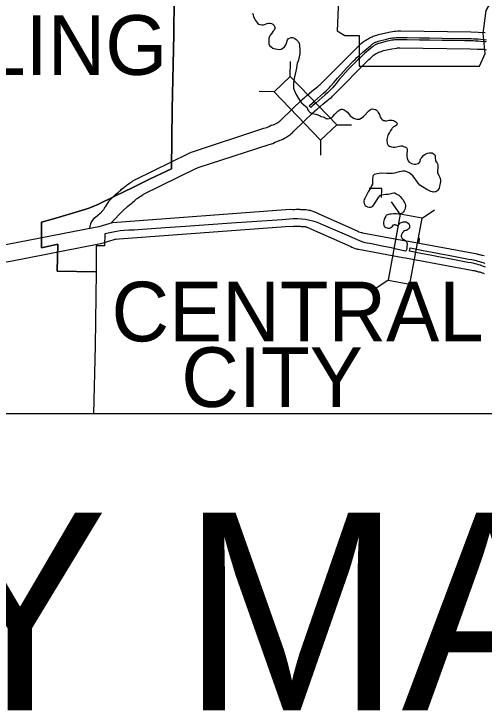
# Model space of a CAD drawing. Extents: x 535214 to 694517, y 381272 to 484355.
# Drawn here: x 552790 to 556953, y 445525 to 451713 of the extents above; entities that cross this region are included whole.
import ezdxf

# ---------------------------------------------------------------- set-up
doc = ezdxf.new("R2010")
doc.units = 0
for name, color, linetype in [('1', 7, 'Continuous'), ('2', 7, 'Continuous'), ('Level 10', 7, 'Continuous'), ('Level 20', 7, 'Continuous'), ('Level 21', 7, 'Continuous'), ('Level 6', 7, 'Continuous'), ('Level 7', 7, 'Continuous')]:
    doc.layers.add(name, color=color, linetype=linetype)

msp = doc.modelspace()

# ---------------------------------------------------------------- linework, layer by layer
at = {"layer": '1'}
msp.add_lwpolyline([(535213.7, 480223.3), (566227, 480223.3), (566227, 448175.2), (535213.7, 448175.2)], close=True, dxfattribs=at)
at = {"layer": 'Level 10'}
for points in [[(553627.3, 450054.3), (553650, 450077.3), (553695.3, 450119.9), (553714.8, 450136.9), (553727.9, 450148), (553734.9, 450153.3), (553742.6, 450161.9), (553763.7, 450177.8), (553769.6, 450182.9), (553777.5, 450189.5), (553785.4, 450195.8), (553791, 450199.8), (553803, 450209.4), (553811.6, 450214), (553813.4, 450215.2), (553822.8, 450222.5), (553832.4, 450228.2), (553839.5, 450232.9), (553843.2, 450235.5), (553849, 450240.4), (553864.5, 450249.5), (554334.5, 450479.1), (554346.9, 450485.2), (554357.7, 450489.5), (554369.6, 450494.4), (555003.6, 450701.2), (555027.7, 450708.7), (555041.3, 450714.9), (555048.4, 450717.2), (555052.8, 450719.3), (555068, 450728), (555081.9, 450731.4), (555085, 450732.6), (555094.1, 450736.5), (555100.8, 450738.7), (555105.7, 450741.1), (555112.8, 450744.6), (555119, 450748.3), (555122.5, 450750.4), (555125.4, 450752.6), (555135.2, 450759), (555140.5, 450762.3), (555142, 450763.4), (555146, 450766.5), (555153.1, 450772.6), (555154.3, 450773.4), (555158.7, 450778.4), (555339.9, 450953.1), (555344.1, 450957), (555348.6, 450962.5), (555358.6, 450971.4), (555365.2, 450977), (555370.8, 450981.2), (555379, 450987.5), (555383.9, 450990.8), (555428.4, 451029), (555479.8, 451071.9), (555489.3, 451078.9), (555494.9, 451083.1), (555498.8, 451086.1), (555502.9, 451089.5), (555505, 451092.1), (555512.9, 451100.5), (555830.9, 451419.9), (555840.8, 451428.5), (555846.4, 451434.1), (555851.7, 451438.9), (555856.2, 451443.8), (555866.5, 451453.9), (555878.9, 451463.2), (555886.5, 451468.9), (555895.2, 451475), (555902.4, 451479.9), (555913.5, 451489), (555926.5, 451494.8), (555935.9, 451499.6), (555945.2, 451504.7), (555957.5, 451510), (555963.5, 451512.4), (555972, 451516.1), (555982.1, 451520), (555992.7, 451523.7), (556002.1, 451526.7), (556009, 451529.3), (556018.8, 451533.1), (556109.1, 451553.9), (556156.4, 451560.2), (556167.1, 451562.1), (556187.3, 451564.5), (556200, 451565.7), (556213.2, 451564.4), (556215.8, 451564.2), (556835.8, 451554.5), (556900.3, 451551.4), (556961.9, 451550.3)], [(553653.4, 449866.8), (553754.8, 449970), (553796, 450008.7), (553812.8, 450023.3), (553821.9, 450031), (553837, 450042.5), (553844.4, 450050.8), (553857.5, 450060.7), (553866.6, 450068.4), (553872.9, 450073.7), (553876.1, 450076.3), (553881.5, 450080.1), (553885.6, 450083.4), (553890, 450085.7), (553902.3, 450094.4), (553907, 450098), (553912.4, 450101.2), (553924.4, 450109.3), (553934.8, 450116.5), (553935.9, 450117.5), (554400.4, 450344.3), (554408, 450348.1), (554414.2, 450350.6), (554421.4, 450353.5), (555049.2, 450558.3), (555081.2, 450568.3), (555095.6, 450574.8), (555103.5, 450577.4), (555122.2, 450586.1), (555122.7, 450586.4), (555141.1, 450593.4), (555148, 450596.4), (555158.4, 450599.9), (555171.6, 450606.4), (555184.5, 450612.7), (555196.4, 450619.8), (555206, 450625.6), (555211.1, 450629.4), (555216.3, 450632.8), (555225.1, 450638.4), (555231.7, 450643.2), (555240.7, 450650), (555242.7, 450651.8), (555252.5, 450657.9), (555267.3, 450674.8), (555442.7, 450843.9), (555453.6, 450853.9), (555457.2, 450858.3), (555457.2, 450858.4), (555458.7, 450859.6), (555461.2, 450861.4), (555467.1, 450866), (555475.2, 450871.5), (555525.3, 450914.5), (555572.4, 450953.8), (555579.1, 450958.7), (555586.5, 450964.3), (555592.7, 450969.2), (555600.4, 450975.5), (555610.8, 450984.7), (555617.7, 450992.9), (555620.9, 450996.4), (555933.7, 451310.5), (555943, 451318.7), (555949.4, 451325), (555957.2, 451332.1), (555963.8, 451339.1), (555964.6, 451340), (555969.2, 451343.4), (555974.8, 451347.7), (555980.1, 451351.4), (555992, 451359.4), (555993.4, 451360.5), (556006.7, 451367.3), (556011.5, 451370), (556015.2, 451371.6), (556021.2, 451374), (556028.7, 451377.2), (556033.7, 451379.2), (556040.1, 451381.4), (556051.8, 451385.1), (556062.9, 451389.3), (556063.1, 451389.4), (556135.9, 451406.2), (556179.5, 451412), (556186, 451413.2), (556186.9, 451413.2), (556200.1, 451414.1), (556202.4, 451414.8), (556207.1, 451414.3), (556831, 451404.5), (556895.3, 451401.5), (556950.5, 451400.5), (556973.1, 451397.4)], [(553627.3, 450054.3), (553596.4, 450006.7), (553592.6, 449999), (553588.2, 449991.5), (553583.2, 449981.1), (553583.1, 449980.8), (553575.4, 449973), (553552.9, 449947.6), (553512.8, 449913.2), (553496.9, 449901.9), (553476.5, 449875.1), (553467.3, 449855), (553464.1, 449845), (553462.8, 449839.4), (553459.9, 449828.9), (553459.4, 449816.5)], [(553661.2, 449868), (555236.1, 449984.7), (555255.6, 449983.5), (555262.6, 449983.8), (555273.5, 449983.7), (555285.7, 449984.5), (555296, 449984.9), (555306.4, 449985.6), (555320.9, 449984.6), (555326.9, 449984), (555335.2, 449983.5), (555339.4, 449983.1), (555347.8, 449983), (555353.6, 449982.4), (555363.8, 449983.4), (555377.8, 449981.4), (555388.2, 449980.7), (555401.7, 449977.8), (555410.5, 449975.7), (555419.2, 449973.3), (555428.9, 449970.6), (555441.3, 449966.4), (555465.2, 449954.8), (555471.1, 449952.4), (555477.4, 449948.8), (555477.5, 449948.8), (555482.3, 449947), (555833.7, 449791.2), (555844.2, 449786.4), (555864.6, 449780), (555865, 449780), (555871.4, 449778.8), (555876.7, 449777.2), (556259.6, 449706.4), (556282.7, 449702.2)], [(551947.1, 449556.7), (551959.7, 449553.7), (551961.7, 449553.6), (551974.2, 449552.3), (551974.5, 449552.2), (551986.8, 449554.7), (551992.5, 449554.3), (551995.8, 449555.1), (552007.2, 449556.9), (552013.1, 449557.5), (552021, 449558.5), (552028.2, 449559.5), (552732.4, 449674.4), (553508.6, 449825), (553543.4, 449833.1), (553661.2, 449868)], [(553680.4, 449719), (555236.9, 449834.4), (555254.4, 449833.3), (555265.4, 449833.8), (555277.5, 449833.7), (555293.2, 449834.6), (555303.9, 449835.1), (555306.4, 449835.2), (555308.9, 449835.1), (555314.9, 449834.5), (555323.6, 449833.9), (555332.3, 449833.2), (555338.9, 449833.1), (555353, 449831.6), (555360.4, 449832.3), (555367.3, 449831.8), (555368.8, 449831.5), (555372.9, 449830.5), (555379.2, 449828.8), (555383.5, 449827.6), (555398.4, 449819.9), (555405.9, 449817), (555408.5, 449815.4), (555419.4, 449810.4), (555425.5, 449808.1), (555772.2, 449654.4), (555782.8, 449649.5), (555796, 449642.3), (555810.7, 449638.5), (555822.9, 449635.9), (555826.9, 449634.7), (555835.9, 449632.8), (555840.7, 449631.3), (556232.4, 449558.9), (556255.6, 449554.6)], [(551913.1, 449410.6), (551937.6, 449404.9), (551948.6, 449404.1), (551953.1, 449403.7), (551968.4, 449400.9), (551996.6, 449403.5), (552026.9, 449408.1), (552030.9, 449408.6), (552040.1, 449409.8), (552049.8, 449411), (552758.8, 449526.7), (553539.8, 449678.2), (553581.7, 449688), (553618.2, 449698.8)], [(553618.2, 449698.8), (553696.2, 449721.9)], [(556283.2, 449702.1), (556876.7, 449593), (556888.7, 449589.4), (556894, 449588.4), (556900.7, 449587), (556908.9, 449585.6), (556925, 449581.4), (556931.5, 449579.2), (556939, 449578.3), (556952.6, 449575)], [(556256.1, 449554.5), (556841.3, 449447), (556853.2, 449443.4), (556864.9, 449441.2), (556873.2, 449439.5), (556877.9, 449438.7), (556881.7, 449437.7), (556888.4, 449435.4), (556901.7, 449431.6), (556912.5, 449430.4), (556915.9, 449429.6), (556916.4, 449429.4), (556920.9, 449427.6), (556930.4, 449425), (556937.1, 449422.2), (556948.5, 449418.8), (556954.7, 449417.2)]]:
    msp.add_lwpolyline(points, dxfattribs=at)
at = {"layer": 'Level 20'}
for p, q in [((555235.6, 451160.9), (555238, 451292.9)), ((555093, 451023.5), (554961.1, 451025.9)), ((555647.9, 450733.4), (555779.9, 450731)), ((555505.4, 450595.9), (555503, 450463.9)), ((556209.5, 449941.3), (556134.5, 450050)), ((556404.2, 449905.6), (556512.9, 449980.5)), ((556102.1, 449357.1), (555993.4, 449282.2)), ((556296.8, 449321.3), (556371.8, 449212.7))]:
    msp.add_line(p, q, dxfattribs=at)
for points in [[(555093, 451023.5), (555505.4, 450595.9), (555647.9, 450733.4), (555235.6, 451160.9)], [(556296.8, 449321.3), (556404.2, 449905.6), (556209.5, 449941.3), (556102.1, 449357.1)]]:
    msp.add_lwpolyline(points, close=True, dxfattribs=at)
at = {"layer": 'Level 21'}
msp.add_lwpolyline([(555608.6, 452842.5), (555684.7, 452335), (555650.9, 451565.2), (555718.6, 451522.9), (555845.5, 451522.9), (555845.5, 451252.3), (556911.3, 451252.3), (556962, 451362.2), (556945.1, 451539.9), (556970.5, 451742.9), (557063.5, 451903.6), (557122.8, 452022), (557207.3, 452148.9), (557258.1, 452284.2), (557300.4, 452394.2), (557376.5, 452487.3), (557393.4, 452546.5), (557359.6, 452588.8), (557097.4, 452588.8), (557156.6, 452707.2), (557165.1, 452783.3), (557130, 452841.8)], close=True, dxfattribs=at)
at = {"layer": 'Level 6'}
for points in [[(553516.2, 449432.2), (553171, 449435.8), (553179.4, 449676.5), (553033, 449642.7), (553032.9, 449869.9), (553139.5, 449901.2), (553299.4, 449948.6), (553417.9, 449982.5), (553461, 449997.7), (553532.1, 450027.3), (553682.7, 450101.8), (553842.6, 450177.2), (553996.5, 450253.4), (554183.4, 450342.7), (554189.4, 450872.1), (554204.8, 451531.8), (554212.8, 452489.9), (554213, 452509.9)], [(554213, 452509.9), (554212.8, 452489.9), (554204.8, 451531.8), (554189.4, 450872.1), (554183.4, 450342.7), (553996.5, 450253.4), (553842.6, 450177.2), (553682.7, 450101.8), (553532.1, 450027.3), (553461, 449997.7), (553417.9, 449982.5), (553299.4, 449948.6), (553139.5, 449901.2), (553032.9, 449869.9), (553033, 449642.7), (553179.4, 449676.5), (553171, 449435.8), (553516.2, 449432.2)], [(554902.8, 451717.6), (554907.6, 451711.3), (554908.6, 451704.5), (554912, 451689.4), (554923.2, 451668), (554928, 451654.9), (554936.8, 451643.2), (554947, 451633), (554958.2, 451624.7), (554971.3, 451619.4), (554983.9, 451617), (554991.7, 451616.5), (555000, 451617.9), (555032.6, 451629.6), (555047.6, 451631.6), (555059.8, 451631.6), (555069.5, 451627.7), (555081.6, 451621.8), (555093.8, 451612.1), (555097.2, 451604.3), (555099.6, 451592.1), (555098.7, 451583.9), (555094.8, 451571.2), (555082.6, 451557.6)], [(555082.6, 451557.6), (555072.9, 451544), (555059.8, 451527), (555053.5, 451514.8), (555047.1, 451499.2), (555045.7, 451485.1), (555045.7, 451466.2), (555047.6, 451448.2), (555053.9, 451435), (555066.1, 451423.4), (555082.1, 451411.7), (555103, 451405.8), (555120, 451402.4), (555140, 451399.5), (555155, 451402.4), (555170.6, 451411.7), (555184.7, 451422.4), (555196.9, 451438.9), (555203.7, 451455.9), (555209, 451476.4), (555212.9, 451485.1), (555219.2, 451493.9), (555228.4, 451500.7), (555244, 451505.6), (555255.2, 451504.1), (555264.9, 451501.7), (555278, 451496.8), (555289.2, 451489), (555298.4, 451479.8), (555308.7, 451467.6), (555315, 451452.1), (555317.4, 451439.4), (555318.4, 451421.9), (555319.8, 451408.8), (555322.3, 451392.7), (555322.3, 451369.8), (555321.3, 451359.1), (555319.3, 451348), (555310.1, 451304.7), (555302.8, 451289.1), (555298, 451274.5), (555294.6, 451259.9), (555290.7, 451234.6), (555271.7, 451141.7), (555266.4, 451107.7), (555264.9, 451090.6), (555264.4, 451076), (555265.9, 451058), (555267.3, 451047.8), (555273.2, 451032.7)], [(556014.9, 451471.4), (556090, 451490.7), (556108.9, 451495.2), (556121.3, 451498), (556131.1, 451500), (556140.7, 451501.5), (556150, 451502.5), (556162, 451503.6), (556174.2, 451504.5), (556201.1, 451505.1), (556231.3, 451505.5), (556273.1, 451505.1), (556381.3, 451502.4), (556470.8, 451501.2), (556581.2, 451499.4), (556673.9, 451497.8), (556783.9, 451496.3), (556840.9, 451495), (556858.4, 451494.5), (556874.3, 451493.7), (556900.6, 451492.1), (556924, 451490.6), (556950.2, 451488.2), (556974, 451485.7)], [(556971.7, 451465.8), (556948.2, 451468.3), (556922.4, 451470.6), (556899.4, 451472.1), (556873.2, 451473.7), (556857.6, 451474.5), (556840.4, 451475), (556783.6, 451476.3), (556673.6, 451477.8), (556580.9, 451479.4), (556470.5, 451481.2), (556381, 451482.4), (556272.8, 451485.1), (556231.4, 451485.5), (556201.5, 451485.1), (556175.2, 451484.5), (556163.6, 451483.7), (556152, 451482.6), (556143.3, 451481.7), (556134.6, 451480.3), (556125.5, 451478.4), (556113.5, 451475.7), (556094.8, 451471.3), (556019.9, 451452)], [(555418.3, 450886.5), (555404.8, 450901.2), (555426.5, 450920.5), (555451.5, 450942.3), (555531.6, 451011.9), (555551.5, 451029.6), (555567.6, 451044.6), (555576.1, 451053.1), (555583.9, 451061.3), (555594.1, 451073), (555626.4, 451110.8), (555654.8, 451145.8), (555738.3, 451237.3), (555796, 451297.5), (555813.7, 451314.7), (555826.3, 451326.8), (555845.1, 451344.1), (555881.8, 451377.3), (555949, 451435.3), (555957.9, 451442.4), (555964.6, 451447.4), (555969.4, 451450.7), (555973.6, 451453.6), (555978.5, 451456.6), (555983.7, 451459.5), (555989.8, 451462.5), (555995.5, 451464.9), (556002.4, 451467.6), (556009.2, 451469.9), (556014.9, 451471.4)], [(556019.9, 451452), (556015, 451450.7), (556009.2, 451448.8), (556003, 451446.4), (555998.1, 451444.3), (555993, 451441.8), (555988.6, 451439.3), (555984.5, 451436.8), (555980.7, 451434.2), (555976.3, 451431.2), (555970.1, 451426.5), (555961.8, 451419.9), (555895.1, 451362.3), (555858.6, 451329.4), (555840.1, 451312.2), (555827.6, 451300.3), (555810.2, 451283.4), (555752.9, 451223.6), (555670, 451132.7), (555641.7, 451098), (555609.2, 451059.9), (555598.7, 451047.9), (555590.4, 451039.2), (555581.5, 451030.3), (555565, 451014.8), (555544.8, 450996.9), (555464.6, 450927.2), (555439.7, 450905.5), (555418.3, 450886.5)], [(555273.2, 451032.7), (555288.2, 451001.1), (555308.2, 450965.6), (555320.8, 450948.1), (555337.3, 450927.7), (555356.3, 450910.2), (555372.3, 450897), (555384.5, 450888.8), (555389.8, 450874.7), (555395.2, 450860.1), (555401.5, 450852.3), (555409.3, 450844), (555418, 450837.7), (555431.6, 450833.3), (555461.8, 450825.5), (555479.3, 450819.7), (555501.1, 450810.4), (555510.9, 450807), (555527.9, 450803.6), (555537.6, 450800.2), (555545.4, 450795.4), (555553.6, 450789), (555560, 450787.1), (555567.7, 450786.6), (555580.4, 450787.6), (555593.5, 450791), (555605.2, 450797.3), (555612.9, 450806.6), (555628, 450824.1), (555648.9, 450843.5), (555662, 450856.2), (555675.2, 450864), (555687.8, 450869.8), (555696.1, 450870.3), (555704.8, 450868.8), (555713.6, 450865.9), (555732.5, 450853.3), (555743.7, 450843), (555757.3, 450823.1), (555767.5, 450811.4), (555784, 450798.8), (555796.2, 450791.5), (555813.2, 450786.1), (555827.3, 450782.7), (555839.5, 450781.7), (555848.2, 450783.7), (555863.8, 450792), (555884.2, 450806.6), (555931.3, 450855.2), (555945.9, 450868.8), (555952.7, 450871.2), (555962.4, 450872.7)], [(555962.4, 450872.7), (555977.5, 450872.2), (555990.6, 450868.8), (555999.4, 450861.5), (556008.1, 450854.2), (556016.4, 450840.6), (556028.1, 450822.6), (556031, 450808.5), (556034.4, 450796.8), (556041.7, 450787.1), (556049.9, 450780.8), (556062.6, 450771.5), (556070.3, 450769.1), (556079.1, 450768.1), (556089.8, 450767.6), (556101, 450770.6), (556113.1, 450773.5), (556129.6, 450774.4), (556139.9, 450774), (556150.6, 450771.5), (556162.7, 450765.7), (556171.9, 450758.9), (556179.7, 450749.6), (556182.1, 450740.9), (556181.7, 450736), (556180.2, 450730.7), (556174.9, 450725.3), (556167.6, 450721.9), (556158.3, 450717.5), (556150.6, 450713.6), (556139.4, 450702), (556135, 450696.6), (556123.8, 450682), (556114.1, 450665), (556104.9, 450646.5), (556101, 450637.3), (556096.6, 450625.6), (556093.7, 450614.9), (556092.2, 450602.7), (556092.2, 450591.1), (556094.2, 450577.9), (556096.1, 450566.3), (556101.9, 450555.6), (556106.8, 450548.7), (556115.6, 450543.4), (556133.1, 450536.6), (556147.1, 450534.1), (556163.7, 450533.7), (556178.3, 450536.1), (556205, 450543.4)], [(556205, 450543.4), (556216.7, 450545.3), (556226.4, 450545.3), (556238.5, 450541.4), (556250.7, 450537.6), (556263.3, 450530.7), (556268.7, 450525.4), (556271.1, 450518.6), (556272.1, 450501.1), (556270.1, 450476.7), (556268.7, 450453.9), (556270.6, 450437.3), (556273.5, 450427.1), (556280.3, 450413), (556291, 450401.4), (556310, 450391.1), (556323.1, 450385.8), (556333.8, 450384.3), (556344.5, 450384.3), (556356.7, 450386.3), (556369.3, 450390.2), (556377.6, 450397), (556386.8, 450408.6), (556389.7, 450425.2), (556392.6, 450433), (556400.4, 450443.2), (556420.3, 450464.6), (556437.8, 450476.7), (556451, 450481.1), (556470.4, 450485.5), (556482.5, 450485), (556492.3, 450483.1), (556501.5, 450479.2), (556508.8, 450471.4), (556515.6, 450465.1), (556518.5, 450458.3), (556519.5, 450448), (556520.9, 450434.9), (556521.4, 450422.8), (556523.9, 450413.5), (556528.7, 450403.8), (556536.5, 450392.1), (556542.3, 450382.4), (556543.8, 450374.6), (556543.8, 450361.9), (556542.3, 450341), (556541.4, 450334.7), (556539.4, 450327.4), (556539.9, 450319.1), (556541.4, 450308.4), (556545.3, 450297.7), (556551.1, 450284.1)], [(556551.1, 450284.1), (556556.9, 450272), (556560.8, 450265.1), (556564.2, 450256.9), (556566.6, 450248.1), (556566.2, 450233.5), (556563.7, 450212.1), (556558.9, 450188.8), (556554.5, 450172.2), (556549.6, 450161.5), (556541.4, 450149.4), (556534.1, 450144.5), (556525.3, 450139.6), (556517.5, 450137.7), (556506.4, 450137.2), (556495.7, 450139.2), (556482.1, 450143.1), (556465, 450150.8), (556447.1, 450160.6), (556409.1, 450183.4), (556384.8, 450198.5), (556369.8, 450215.5), (556341.6, 450254.4), (556322.6, 450281.2), (556305.6, 450296.8), (556290.5, 450306.5), (556270.1, 450317.2), (556255.5, 450321.1), (556246.8, 450322.1), (556233.2, 450320.6), (556219.1, 450318.2), (556201.6, 450315.3), (556159.8, 450304.5), (556141.3, 450301.6), (556090.3, 450302.6), (556046, 450304.5), (556023.7, 450302.6), (556005.2, 450299.7), (555994.5, 450296.8), (555980.4, 450291.4), (555971.7, 450282.7), (555968.3, 450276.8), (555966.3, 450270), (555965.4, 450257.4), (555965.8, 450240.3), (555965.8, 450221.4), (555963.9, 450208.2), (555957.1, 450193.2), (555945.4, 450164.9), (555927.9, 450138.2)], [(555927.9, 450138.2), (555917.2, 450122.1), (555904.6, 450096.8), (555895.8, 450078.8), (555892.4, 450070.1), (555889.5, 450058.4), (555889, 450048.2), (555890, 450037), (555892.9, 450029.2), (555898.8, 450017.1), (555908, 450010.7), (555919.2, 450005.4), (555936.2, 450002), (555945.9, 450003), (555957.6, 450005.4), (555963.9, 450009.8), (555976.5, 450024.8), (556017.4, 450089.1), (556033.9, 450105.6), (556048, 450112.9), (556063.1, 450116.8), (556082, 450119.2), (556103.9, 450118.2), (556117, 450120.7), (556131.1, 450124.1), (556139.9, 450128.5), (556152.5, 450130.9), (556162.2, 450129.4), (556170.5, 450125.5), (556177.3, 450117.8), (556182.6, 450115.3), (556190.9, 450113.9), (556199.2, 450109), (556209.4, 450098.8), (556224.9, 450081.3), (556232.7, 450070.1), (556248, 450045.2), (556253.1, 450032), (556255.8, 450021.3), (556256, 450009.3), (556254.8, 449994.1), (556252.1, 449983.5), (556246.3, 449971.8), (556236.1, 449959.3), (556226.4, 449950.1), (556213.7, 449943.6), (556205.7, 449941.5), (556194.5, 449942.3), (556178.7, 449943.7), (556164.9, 449944.2), (556150.6, 449943.7), (556131.6, 449942.5)], [(556131.6, 449942.5), (556117.5, 449941.1), (556106.8, 449939.4), (556096.4, 449936.4), (556088.8, 449931.6), (556085.9, 449928.7), (556081.8, 449923.5), (556073, 449907.5), (556067.7, 449893.4), (556064.5, 449882.7), (556062.3, 449870.3), (556061.8, 449862.7), (556063.1, 449854.5), (556065.5, 449844.3), (556069.6, 449836), (556075, 449828.4), (556083.7, 449823.6), (556094.4, 449819.4), (556100, 449818.2), (556106.1, 449817.7), (556117, 449818), (556124.3, 449820.5), (556131.1, 449823.8), (556135, 449827.4), (556137.9, 449829.7), (556144.7, 449839.5), (556150.1, 449845.8), (556154, 449847.4), (556158.3, 449848.8), (556162.7, 449848.9), (556167.1, 449848.3), (556171, 449847.2), (556176.8, 449844.4), (556182.1, 449840.5), (556187, 449841), (556191.9, 449843.8), (556196.7, 449849.2), (556199.9, 449852.3), (556207.7, 449861.5), (556214.2, 449865.7), (556230.5, 449870), (556239.7, 449873), (556247, 449874.4), (556254.8, 449873.9), (556262.8, 449872.6), (556271.8, 449868.6), (556281.3, 449861.9), (556289.6, 449851.2), (556292.5, 449844.9), (556293.9, 449837.6), (556293.7, 449829.2), (556292, 449822), (556288.4, 449815.6), (556281.8, 449809), (556273.5, 449801.6), (556266, 449797.8), (556257, 449795.6), (556248.3, 449792.7), (556240, 449786.9), (556235.4, 449782.5), (556231, 449777.6), (556224.4, 449766.9), (556222.2, 449761.8), (556220.3, 449755.5), (556219.6, 449751.1), (556219.3, 449747.7), (556220.1, 449740.6), (556223.7, 449733.6), (556228.8, 449726.5), (556236.1, 449719.7), (556249.2, 449713.6), (556258.9, 449705.3), (556263.6, 449699.8), (556266.2, 449695.9), (556268.4, 449691.3), (556270.1, 449685.8), (556271.3, 449681.1), (556271.6, 449676.4), (556270.9, 449665.7), (556270.1, 449660.9), (556269.2, 449654.7), (556268.4, 449641.7), (556266.3, 449625.3), (556262.8, 449621.2), (556258.9, 449618.2), (556253.8, 449614.9)], [(556253.8, 449614.9), (556214.6, 449622.5), (556177.6, 449630.6), (556130.8, 449643.7), (556051.3, 449657.8), (555954.9, 449677.4), (555900.5, 449688.3), (555873.3, 449696.5), (555811.3, 449722.6), (555738.4, 449754.8), (555531.5, 449844.1), (555476.5, 449866.4), (555439.5, 449879), (555411.2, 449886), (555372, 449893.7), (555335.5, 449898), (555299.6, 449900.2), (555261.5, 449899.1), (555164.1, 449892.6), (555077, 449886.6), (554715, 449862.1), (554309.5, 449833.2), (554173.2, 449822.9), (553964.9, 449809.2), (553889.3, 449802.7), (553854.4, 449801.1), (553807.1, 449799.4), (553764.6, 449796.7), (553731.4, 449792.9), (553698.8, 449786.9), (553593.7, 449766.6)], [(553593.7, 449766.6), (553590.9, 449659.9), (553517.1, 449659.7), (553516.2, 449432.2)], [(556292.1, 449613.2), (556297.9, 449642.7), (556413.3, 449620.7), (556479.8, 449608.8), (556554.6, 449594.2), (556680.8, 449570.3), (556815.5, 449544.3), (556844.2, 449538.8), (556859.3, 449535.8), (556870.7, 449533.3), (556882.4, 449530.5), (556897.3, 449526.7), (556913.1, 449522.2), (556929, 449517.3), (556942, 449513.1), (556958.7, 449507.3)], [(556965.6, 449472.5), (556948.3, 449479.1), (556932.5, 449484.7), (556920, 449488.7), (556904.6, 449493.5), (556889.5, 449497.7), (556875.1, 449501.4), (556864, 449504.1), (556853.2, 449506.5), (556838.5, 449509.4), (556809.8, 449514.8), (556675.2, 449540.8), (556548.9, 449564.7), (556474.2, 449579.3), (556407.9, 449591.2), (556292.1, 449613.2)], [(553516.2, 449432.2), (553507.9, 448775.5), (553494.1, 448175.2)]]:
    msp.add_lwpolyline(points, dxfattribs=at)
at = {"layer": 'Level 7'}
for points in [[(556045.3, 450090.3), (556046.1, 450167.2), (555935.8, 450169.1)], [(556378.6, 449686.6), (556379.6, 449725), (556367.2, 449724.9)]]:
    msp.add_lwpolyline(points, dxfattribs=at)

# ---------------------------------------------------------------- texts
at = {"layer": '2'}
msp.add_text('VICINITY MAP', height=1750, dxfattribs=at).set_placement((543741, 445550.2))
at = {"layer": 'Level 6'}
for s, p in [('BARLING', (551047.6, 451174.5)), ('CENTRAL', (553653.3, 448815.4)), ('CITY', (554271.4, 448234.5))]:
    msp.add_text(s, height=528, dxfattribs=at).set_placement(p)

doc.saveas('drawing.dxf')
